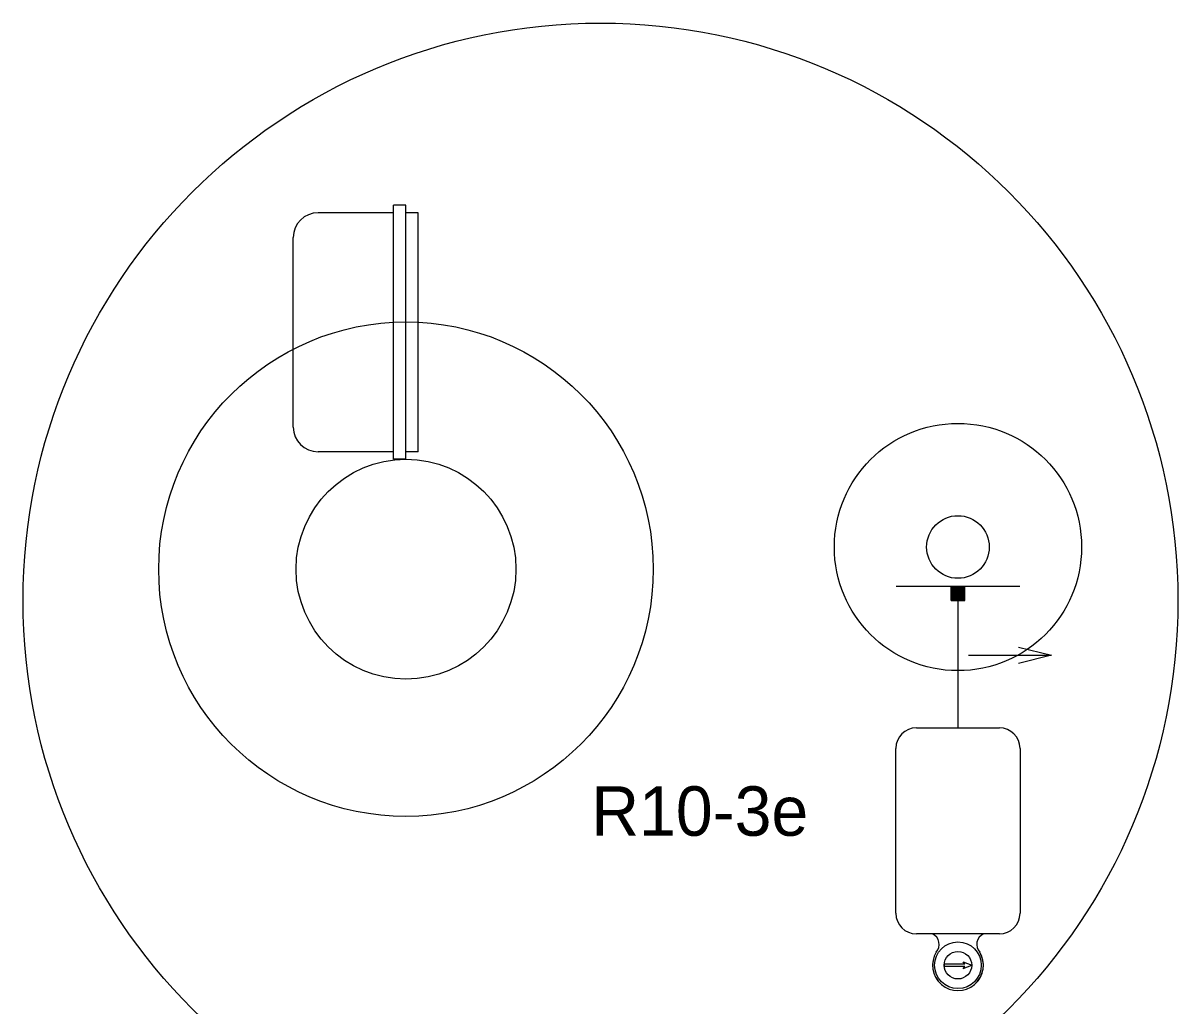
# Model space of a CAD drawing. Extents: x 1695551 to 1695718, y 544410 to 544516.
# Drawn here: x 1695654.45 to 1695671.96, y 544441.23 to 544456.14 of the extents above; entities that cross this region are included whole.
import ezdxf

# ---------------------------------------------------------------- set-up
doc = ezdxf.new("R2010")
doc.units = 0
doc.layers.add('T_Drafting', color=7, linetype='Continuous')

msp = doc.modelspace()

# ---------------------------------------------------------------- linework, layer by layer
at = {"layer": 'T_Drafting'}
for p, q in [((1695660.067, 544453.259), (1695658.921, 544453.259)), ((1695660.067, 544449.52), (1695660.067, 544453.374)), ((1695660.255, 544453.374), (1695660.067, 544453.374)), ((1695660.255, 544449.52), (1695660.255, 544453.374)), ((1695660.442, 544453.259), (1695660.255, 544453.259)), ((1695660.442, 544449.634), (1695660.442, 544453.259)), ((1695658.546, 544450.009), (1695658.546, 544452.884)), ((1695660.067, 544449.634), (1695658.921, 544449.634)), ((1695660.442, 544449.634), (1695660.255, 544449.634)), ((1695660.255, 544449.52), (1695660.067, 544449.52)), ((1695669.563, 544447.59), (1695667.688, 544447.59)), ((1695668.521, 544447.381), (1695668.521, 544447.59)), ((1695668.521, 544447.383), (1695668.728, 544447.59)), ((1695668.521, 544447.386), (1695668.725, 544447.59)), ((1695668.521, 544447.39), (1695668.721, 544447.59)), ((1695668.521, 544447.393), (1695668.718, 544447.59)), ((1695668.521, 544447.397), (1695668.714, 544447.59)), ((1695668.521, 544447.4), (1695668.711, 544447.59)), ((1695668.521, 544447.404), (1695668.707, 544447.59)), ((1695668.521, 544447.407), (1695668.704, 544447.59)), ((1695668.521, 544447.411), (1695668.7, 544447.59)), ((1695668.521, 544447.415), (1695668.696, 544447.59)), ((1695668.521, 544447.418), (1695668.693, 544447.59)), ((1695668.521, 544447.422), (1695668.689, 544447.59)), ((1695668.521, 544447.425), (1695668.686, 544447.59)), ((1695668.521, 544447.429), (1695668.682, 544447.59)), ((1695668.521, 544447.432), (1695668.679, 544447.59)), ((1695668.521, 544447.436), (1695668.675, 544447.59)), ((1695668.521, 544447.439), (1695668.672, 544447.59)), ((1695668.521, 544447.443), (1695668.668, 544447.59)), ((1695668.521, 544447.446), (1695668.665, 544447.59)), ((1695668.521, 544447.45), (1695668.661, 544447.59)), ((1695668.521, 544447.453), (1695668.658, 544447.59)), ((1695668.521, 544447.457), (1695668.654, 544447.59)), ((1695668.521, 544447.461), (1695668.65, 544447.59)), ((1695668.521, 544447.464), (1695668.647, 544447.59)), ((1695668.521, 544447.468), (1695668.643, 544447.59)), ((1695668.521, 544447.471), (1695668.64, 544447.59)), ((1695668.521, 544447.475), (1695668.636, 544447.59)), ((1695668.521, 544447.478), (1695668.633, 544447.59)), ((1695668.521, 544447.482), (1695668.629, 544447.59)), ((1695668.521, 544447.485), (1695668.626, 544447.59)), ((1695668.521, 544447.489), (1695668.622, 544447.59)), ((1695668.521, 544447.492), (1695668.619, 544447.59)), ((1695668.521, 544447.496), (1695668.615, 544447.59)), ((1695668.521, 544447.499), (1695668.612, 544447.59)), ((1695668.521, 544447.503), (1695668.608, 544447.59)), ((1695668.521, 544447.506), (1695668.605, 544447.59)), ((1695668.521, 544447.51), (1695668.601, 544447.59)), ((1695668.521, 544447.514), (1695668.597, 544447.59)), ((1695668.521, 544447.517), (1695668.594, 544447.59)), ((1695668.521, 544447.521), (1695668.59, 544447.59)), ((1695668.521, 544447.524), (1695668.587, 544447.59)), ((1695668.521, 544447.528), (1695668.583, 544447.59)), ((1695668.521, 544447.531), (1695668.58, 544447.59)), ((1695668.521, 544447.535), (1695668.576, 544447.59)), ((1695668.521, 544447.538), (1695668.573, 544447.59)), ((1695668.521, 544447.542), (1695668.569, 544447.59)), ((1695668.521, 544447.545), (1695668.566, 544447.59)), ((1695668.521, 544447.549), (1695668.562, 544447.59)), ((1695668.521, 544447.552), (1695668.559, 544447.59)), ((1695668.521, 544447.556), (1695668.555, 544447.59)), ((1695668.521, 544447.559), (1695668.551, 544447.59)), ((1695668.521, 544447.563), (1695668.548, 544447.59)), ((1695668.521, 544447.567), (1695668.544, 544447.59)), ((1695668.521, 544447.57), (1695668.541, 544447.59)), ((1695668.521, 544447.574), (1695668.537, 544447.59)), ((1695668.521, 544447.577), (1695668.534, 544447.59)), ((1695668.521, 544447.581), (1695668.53, 544447.59)), ((1695668.521, 544447.584), (1695668.527, 544447.59)), ((1695668.521, 544447.588), (1695668.523, 544447.59)), ((1695668.523, 544447.381), (1695668.73, 544447.588)), ((1695668.527, 544447.381), (1695668.73, 544447.584)), ((1695668.531, 544447.381), (1695668.73, 544447.58)), ((1695668.534, 544447.381), (1695668.73, 544447.577)), ((1695668.538, 544447.381), (1695668.73, 544447.573)), ((1695668.541, 544447.381), (1695668.73, 544447.57)), ((1695668.545, 544447.381), (1695668.73, 544447.566)), ((1695668.548, 544447.381), (1695668.73, 544447.563)), ((1695668.552, 544447.381), (1695668.73, 544447.559)), ((1695668.555, 544447.381), (1695668.73, 544447.556)), ((1695668.559, 544447.381), (1695668.73, 544447.552)), ((1695668.562, 544447.381), (1695668.73, 544447.549)), ((1695668.566, 544447.381), (1695668.73, 544447.545)), ((1695668.569, 544447.381), (1695668.73, 544447.542)), ((1695668.573, 544447.381), (1695668.73, 544447.538)), ((1695668.577, 544447.381), (1695668.73, 544447.534)), ((1695668.58, 544447.381), (1695668.73, 544447.531)), ((1695668.584, 544447.381), (1695668.73, 544447.527)), ((1695668.587, 544447.381), (1695668.73, 544447.524)), ((1695668.591, 544447.381), (1695668.73, 544447.52)), ((1695668.594, 544447.381), (1695668.73, 544447.517)), ((1695668.598, 544447.381), (1695668.73, 544447.513)), ((1695668.601, 544447.381), (1695668.73, 544447.51)), ((1695668.605, 544447.381), (1695668.73, 544447.506)), ((1695668.608, 544447.381), (1695668.73, 544447.503)), ((1695668.612, 544447.381), (1695668.73, 544447.499)), ((1695668.615, 544447.381), (1695668.73, 544447.496)), ((1695668.619, 544447.381), (1695668.73, 544447.492)), ((1695668.622, 544447.381), (1695668.73, 544447.489)), ((1695668.626, 544447.381), (1695668.73, 544447.485)), ((1695668.63, 544447.381), (1695668.73, 544447.481)), ((1695668.633, 544447.381), (1695668.73, 544447.478)), ((1695668.637, 544447.381), (1695668.73, 544447.474)), ((1695668.64, 544447.381), (1695668.73, 544447.471)), ((1695668.644, 544447.381), (1695668.73, 544447.467)), ((1695668.647, 544447.381), (1695668.73, 544447.464)), ((1695668.651, 544447.381), (1695668.73, 544447.46)), ((1695668.654, 544447.381), (1695668.73, 544447.457)), ((1695668.658, 544447.381), (1695668.73, 544447.453)), ((1695668.73, 544447.381), (1695668.73, 544447.59)), ((1695668.521, 544447.381), (1695668.73, 544447.381)), ((1695668.626, 544447.381), (1695668.626, 544445.447)), ((1695668.661, 544447.381), (1695668.73, 544447.45)), ((1695668.665, 544447.381), (1695668.73, 544447.446)), ((1695668.668, 544447.381), (1695668.73, 544447.443)), ((1695668.672, 544447.381), (1695668.73, 544447.439)), ((1695668.675, 544447.381), (1695668.73, 544447.435)), ((1695668.679, 544447.381), (1695668.73, 544447.432)), ((1695668.683, 544447.381), (1695668.73, 544447.428)), ((1695668.686, 544447.381), (1695668.73, 544447.425)), ((1695668.69, 544447.381), (1695668.73, 544447.421)), ((1695668.693, 544447.381), (1695668.73, 544447.418)), ((1695668.697, 544447.381), (1695668.73, 544447.414)), ((1695668.7, 544447.381), (1695668.73, 544447.411)), ((1695668.704, 544447.381), (1695668.73, 544447.407)), ((1695668.707, 544447.381), (1695668.73, 544447.404)), ((1695668.711, 544447.381), (1695668.73, 544447.4)), ((1695668.714, 544447.381), (1695668.73, 544447.397)), ((1695668.718, 544447.381), (1695668.73, 544447.393)), ((1695668.721, 544447.381), (1695668.73, 544447.39)), ((1695668.725, 544447.381), (1695668.73, 544447.386)), ((1695668.729, 544447.381), (1695668.73, 544447.382)), ((1695668.787, 544446.548), (1695670.045, 544446.548)), ((1695667.996, 544445.447), (1695669.255, 544445.447)), ((1695667.684, 544442.635), (1695667.684, 544445.135)), ((1695669.567, 544445.135), (1695669.567, 544442.635)), ((1695669.255, 544442.322), (1695667.996, 544442.322)), ((1695668.419, 544441.866), (1695668.419, 544441.828)), ((1695668.732, 544441.866), (1695668.419, 544441.866)), ((1695668.707, 544441.897), (1695668.834, 544441.847)), ((1695668.732, 544441.866), (1695668.707, 544441.897)), ((1695668.707, 544441.797), (1695668.834, 544441.847)), ((1695668.732, 544441.828), (1695668.419, 544441.828)), ((1695668.707, 544441.797), (1695668.732, 544441.828))]:
    msp.add_line(p, q, dxfattribs=at)
msp.add_lwpolyline([(1695669.545, 544446.673), (1695670.045, 544446.548), (1695669.545, 544446.423)], dxfattribs=at)
for centre, radius in [((1695663.205, 544447.379), 8.757), ((1695660.255, 544447.853), 3.75), ((1695668.626, 544448.19), 1.875), ((1695660.255, 544447.853), 1.667), ((1695668.626, 544448.19), 0.475), ((1695668.626, 544441.847), 0.354), ((1695668.626, 544441.847), 0.208)]:
    msp.add_circle(centre, radius, dxfattribs=at)
for centre, radius, start, end in [((1695658.921, 544452.884), 0.375, 90, 180), ((1695658.921, 544450.009), 0.375, 180, 270), ((1695667.996, 544445.135), 0.312, 90, 180), ((1695669.255, 544445.135), 0.312, 0, 90), ((1695667.996, 544442.635), 0.312, 180, 270), ((1695669.255, 544442.635), 0.312, 270, 0), ((1695668.166, 544442.164), 0.175, 318.1972, 64.8044), ((1695669.086, 544442.164), 0.175, 115.1956, 221.8028), ((1695668.626, 544441.847), 0.385, 148.7402, 227.4934), ((1695668.626, 544441.847), 0.385, 148.7402, 31.2598), ((1695668.626, 544441.847), 0.385, 312.5066, 31.2598)]:
    msp.add_arc(centre, radius, start, end, dxfattribs=at)

# ---------------------------------------------------------------- texts
msp.add_text('R10-3e', height=0.75, dxfattribs=at).set_placement((1695663.066, 544443.811))

doc.saveas('drawing.dxf')
